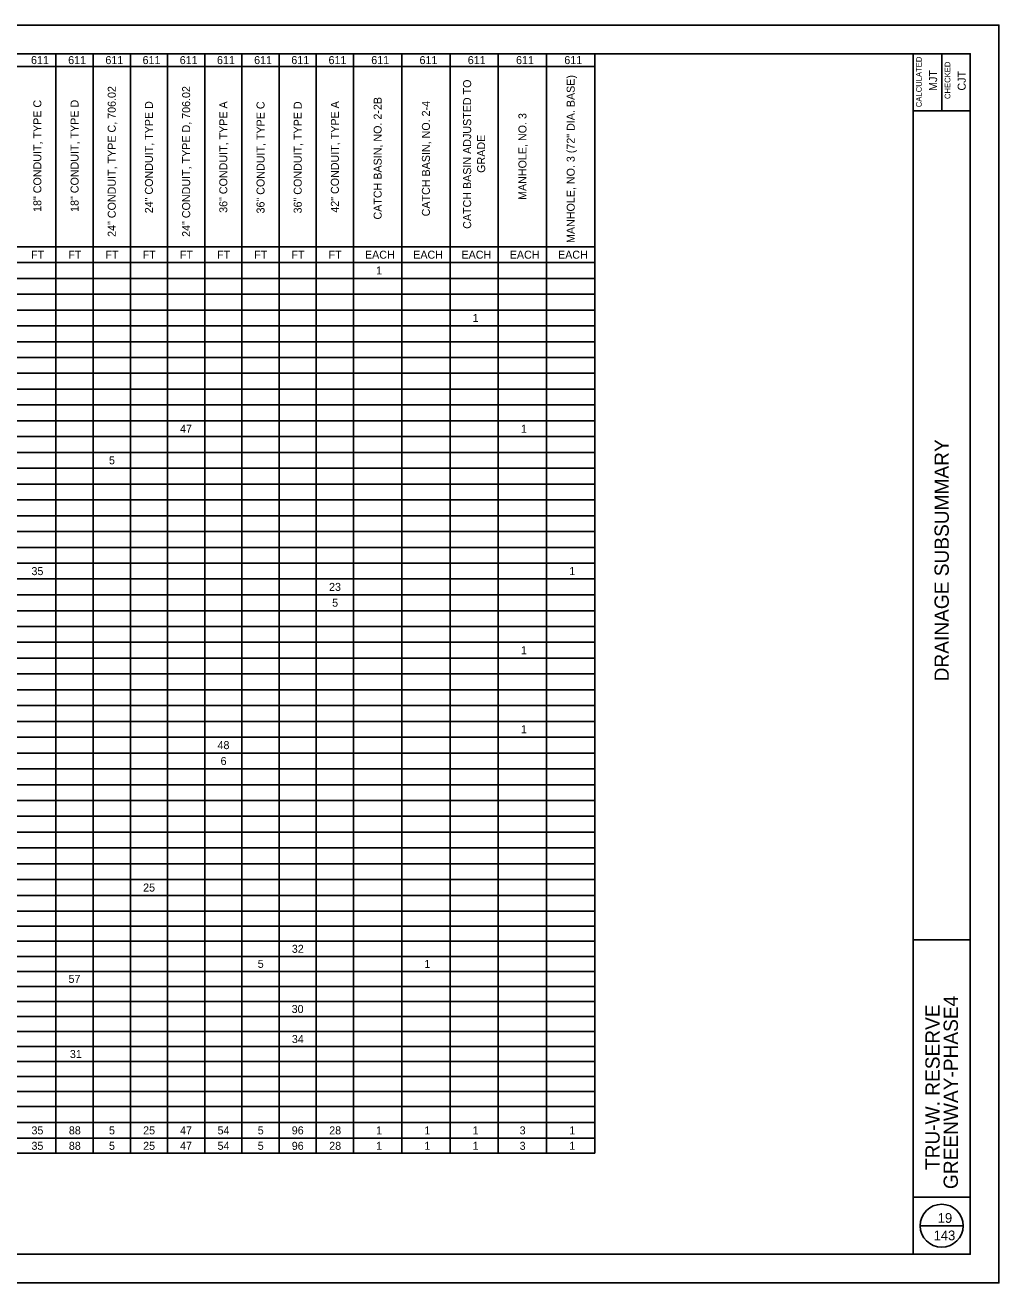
# Model space of a CAD drawing. Extents: x -16 to 102, y -13 to 9.
# Drawn here: x 0.6 to 17.63, y -12.91 to 9.09 of the extents above; entities that cross this region are included whole.
import ezdxf

# ---------------------------------------------------------------- set-up
doc = ezdxf.new("R2010")
doc.units = 0
for name, color, linetype in [('SH_Border', 7, 'Continuous'), ('SH_Cut_Line', 7, 'Continuous'), ('SH_Data', 7, 'Continuous'), ('TX_P_1', 7, 'Continuous')]:
    doc.layers.add(name, color=color, linetype=linetype)

msp = doc.modelspace()

# ---------------------------------------------------------------- linework, layer by layer
at = {"layer": 'SH_Border'}
for p, q in [((16.129, -12.407), (16.129, 8.593)), ((16.629, 8.593), (16.629, 7.593)), ((16.129, 7.593), (17.129, 7.593)), ((16.129, -6.907), (17.129, -6.907)), ((16.129, -11.407), (17.129, -11.407))]:
    msp.add_line(p, q, dxfattribs=at)
msp.add_lwpolyline([(-14.371, 8.593), (17.129, 8.593), (17.129, -12.407), (-14.371, -12.407)], close=True, dxfattribs=at)
at = {"layer": 'SH_Cut_Line'}
msp.add_lwpolyline([(-16.371, -12.907), (17.629, -12.907), (17.629, 9.093), (-16.371, 9.093)], close=True, dxfattribs=at)
at = {"layer": 'SH_Data'}
msp.add_line((16.254, -11.907), (17.004, -11.907), dxfattribs=at)
msp.add_circle((16.629, -11.907), 0.375, dxfattribs=at)
at = {"layer": 'TX_P_1'}
for p, q in [((-14.371, 8.593), (10.564, 8.593)), ((1.141, 8.593), (1.141, -10.641)), ((1.791, 8.593), (1.791, -10.641)), ((2.441, 8.593), (2.441, -10.641)), ((3.092, 8.593), (3.092, -10.641)), ((3.742, 8.593), (3.742, -10.641)), ((4.392, 8.593), (4.392, -10.641)), ((5.043, 8.593), (5.043, -10.641)), ((5.693, 8.593), (5.693, -10.641)), ((6.343, 8.593), (6.343, -10.641)), ((7.188, 8.593), (7.188, -10.641)), ((8.032, 8.593), (8.032, -10.641)), ((8.876, 8.593), (8.876, -10.641)), ((9.72, 8.593), (9.72, -10.641)), ((10.564, 8.593), (10.564, -10.641)), ((-6.442, 8.372), (10.564, 8.372)), ((-6.442, 5.217), (10.564, 5.217)), ((-14.371, 4.94), (10.564, 4.94)), ((-14.371, 4.663), (10.564, 4.663)), ((-14.371, 4.386), (10.564, 4.386)), ((-14.371, 4.11), (10.564, 4.11)), ((-14.371, 3.833), (10.564, 3.833)), ((-14.371, 3.556), (10.564, 3.556)), ((-14.371, 3.279), (10.564, 3.279)), ((-14.371, 3.003), (10.564, 3.003)), ((-14.371, 2.726), (10.564, 2.726)), ((-14.371, 2.449), (10.564, 2.449)), ((-14.371, 2.172), (10.564, 2.172)), ((-14.371, 1.896), (10.564, 1.896)), ((-14.371, 1.619), (10.564, 1.619)), ((-14.371, 1.342), (10.564, 1.342)), ((-14.371, 1.065), (10.564, 1.065)), ((-14.371, 0.789), (10.564, 0.789)), ((-14.371, 0.512), (10.564, 0.512)), ((-14.371, 0.235), (10.564, 0.235)), ((-14.371, -0.042), (10.564, -0.042)), ((-14.371, -0.318), (10.564, -0.318)), ((-14.371, -0.595), (10.564, -0.595)), ((-14.371, -0.872), (10.564, -0.872)), ((-14.371, -1.149), (10.564, -1.149)), ((-14.371, -1.425), (10.564, -1.425)), ((-14.371, -1.702), (10.564, -1.702)), ((-14.371, -1.979), (10.564, -1.979)), ((-14.371, -2.256), (10.564, -2.256)), ((-14.371, -2.532), (10.564, -2.532)), ((-14.371, -2.809), (10.564, -2.809)), ((-14.371, -3.086), (10.564, -3.086)), ((-14.371, -3.363), (10.564, -3.363)), ((-14.371, -3.639), (10.564, -3.639)), ((-14.371, -3.916), (10.564, -3.916)), ((-14.371, -4.193), (10.564, -4.193)), ((-14.371, -4.47), (10.564, -4.47)), ((-14.371, -4.746), (10.564, -4.746)), ((-14.371, -5.023), (10.564, -5.023)), ((-14.371, -5.3), (10.564, -5.3)), ((-14.371, -5.577), (10.564, -5.577)), ((-14.371, -5.853), (10.564, -5.853)), ((-14.371, -6.13), (10.564, -6.13)), ((-14.371, -6.407), (10.564, -6.407)), ((-14.371, -6.67), (10.564, -6.67)), ((-14.371, -6.933), (10.564, -6.933)), ((-14.371, -7.196), (10.564, -7.196)), ((-14.371, -7.458), (10.564, -7.458)), ((-14.371, -7.721), (10.564, -7.721)), ((-14.371, -7.984), (10.564, -7.984)), ((-14.371, -8.247), (10.564, -8.247)), ((-14.371, -8.51), (10.564, -8.51)), ((-14.371, -8.773), (10.564, -8.773)), ((-14.371, -9.036), (10.564, -9.036)), ((-14.371, -9.299), (10.564, -9.299)), ((-14.371, -9.562), (10.564, -9.562)), ((-14.371, -9.825), (10.564, -9.825)), ((-14.371, -10.101), (10.564, -10.101)), ((-14.371, -10.378), (10.564, -10.378)), ((-14.371, -10.641), (10.564, -10.641))]:
    msp.add_line(p, q, dxfattribs=at)

# ---------------------------------------------------------------- texts
at = {"layer": 'SH_Data'}
for s, height, p in [('CALCULATED', 0.1, (16.281, 7.658)), ('CHECKED', 0.1, (16.781, 7.801)), ('MJT', 0.14, (16.549, 7.942)), ('CJT', 0.14, (17.049, 7.949)), ('DRAINAGE SUBSUMMARY', 0.25, (16.754, -2.386)), ('GREENWAY-PHASE4', 0.25, (16.913, -11.266)), ('TRU-W. RESERVE', 0.25, (16.594, -10.934))]:
    msp.add_text(s, height=height, rotation=90, dxfattribs=at).set_placement(p)
for s, p in [('19', (16.56, -11.857)), ('143', (16.488, -12.162))]:
    msp.add_text(s, height=0.17, dxfattribs=at).set_placement(p)
at = {"layer": 'TX_P_1'}
for s, p in [('611', (0.704, 8.412)), ('611', (1.354, 8.412)), ('611', (2.005, 8.412)), ('611', (2.655, 8.412)), ('611', (3.305, 8.412)), ('611', (3.956, 8.412)), ('611', (4.606, 8.412)), ('611', (5.256, 8.412)), ('611', (5.907, 8.412)), ('611', (6.654, 8.412)), ('611', (7.498, 8.412)), ('611', (8.342, 8.412)), ('611', (9.186, 8.412)), ('611', (10.03, 8.412)), ('FT', (0.705, 5.008)), ('FT', (1.356, 5.008)), ('FT', (2.006, 5.008)), ('FT', (2.656, 5.008)), ('FT', (3.307, 5.008)), ('FT', (3.957, 5.008)), ('FT', (4.607, 5.008)), ('FT', (5.258, 5.008)), ('FT', (5.908, 5.008)), ('EACH', (6.544, 5.008)), ('EACH', (7.388, 5.008)), ('EACH', (8.232, 5.008)), ('EACH', (9.076, 5.008)), ('EACH', (9.92, 5.008)), ('1', (6.739, 4.732)), ('1', (8.427, 3.901)), ('47', (3.311, 1.964)), ('1', (9.272, 1.964)), ('5', (2.068, 1.411)), ('35', (0.712, -0.527)), ('1', (10.116, -0.527)), ('23', (5.916, -0.803)), ('5', (5.97, -1.08)), ('1', (9.272, -1.91)), ('1', (9.272, -3.294)), ('48', (3.966, -3.571)), ('6', (4.019, -3.848)), ('25', (2.665, -6.062)), ('32', (5.265, -7.134)), ('5', (4.669, -7.397)), ('1', (7.583, -7.397)), ('57', (1.36, -7.66)), ('30', (5.262, -8.186)), ('34', (5.266, -8.712)), ('31', (1.384, -8.974)), ('35', (0.712, -10.31)), ('88', (1.366, -10.31)), ('5', (2.068, -10.31)), ('25', (2.665, -10.31)), ('47', (3.311, -10.31)), ('54', (3.966, -10.31)), ('5', (4.669, -10.31)), ('96', (5.264, -10.31)), ('28', (5.919, -10.31)), ('1', (6.739, -10.31)), ('1', (7.583, -10.31)), ('1', (8.427, -10.31)), ('3', (9.249, -10.31)), ('1', (10.116, -10.31)), ('35', (0.712, -10.58)), ('88', (1.366, -10.58)), ('5', (2.068, -10.58)), ('25', (2.665, -10.58)), ('47', (3.311, -10.58)), ('54', (3.966, -10.58)), ('5', (4.669, -10.58)), ('96', (5.264, -10.58)), ('28', (5.919, -10.58)), ('1', (6.739, -10.58)), ('1', (7.583, -10.58)), ('1', (8.427, -10.58)), ('3', (9.249, -10.58)), ('1', (10.116, -10.58))]:
    msp.add_text(s, height=0.14, dxfattribs=at).set_placement(p)
for s, height, p in [('MANHOLE, NO. 3 (72" DIA. BASE)', 0.14004, (10.212, 5.282)), ('24" CONDUIT, TYPE C, 706.02', 0.14004, (2.186, 5.39)), ('24" CONDUIT, TYPE D, 706.02', 0.14004, (3.487, 5.39)), ('CATCH BASIN ADJUSTED TO', 0.14004, (8.401, 5.53)), ('18" CONDUIT, TYPE C', 0.14004, (0.885, 5.826)), ('18" CONDUIT, TYPE D', 0.14004, (1.536, 5.827)), ('24" CONDUIT, TYPE D', 0.14004, (2.836, 5.803)), ('36" CONDUIT, TYPE A', 0.14004, (4.137, 5.81)), ('36" CONDUIT, TYPE C', 0.14004, (4.788, 5.799)), ('36" CONDUIT, TYPE D', 0.14004, (5.438, 5.8)), ('42" CONDUIT, TYPE A', 0.14004, (6.088, 5.813)), ('CATCH BASIN, NO. 2-2B', 0.14004, (6.836, 5.693)), ('CATCH BASIN, NO. 2-4', 0.14004, (7.68, 5.749)), ('MANHOLE, NO. 3', 0.14004, (9.368, 6.036)), ('GRADE', 0.14, (8.646, 6.51))]:
    msp.add_text(s, height=height, rotation=90, dxfattribs=at).set_placement(p)

doc.saveas('drawing.dxf')
